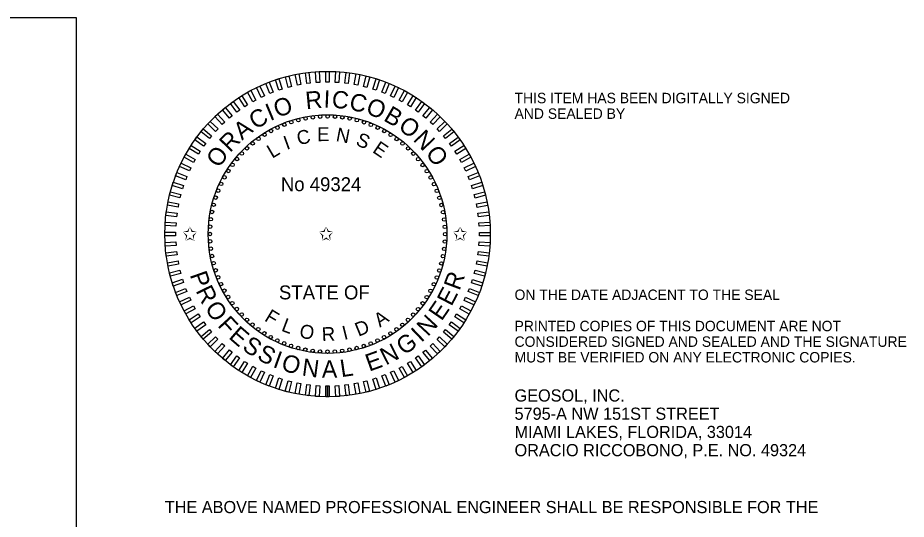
# Model space of a CAD drawing. Extents: x -816.9 to -790.1, y -2199.5 to -2184.5.
# Drawn here: x -795.17 to -790.06, y -2191.79 to -2188.9 of the extents above; entities that cross this region are included whole.
import ezdxf

# ---------------------------------------------------------------- set-up
doc = ezdxf.new("R2010")
doc.units = 0
for name, color, linetype in [('Logo_dp', 7, 'Continuous'), ('NonPlottingEle_dp', 7, 'Continuous'), ('PlotBorder_dp', 7, 'Continuous'), ('TextMisc', 7, 'Continuous')]:
    doc.layers.add(name, color=color, linetype=linetype)

msp = doc.modelspace()

# ---------------------------------------------------------------- linework, layer by layer
at = {"layer": 'Logo_dp'}
for p, q in [((-793.3999, -2191.0843), (-793.4001, -2191.0218)), ((-793.3899, -2191.0843), (-793.3901, -2191.0218)), ((-793.3799, -2191.0843), (-793.3801, -2191.0218))]:
    msp.add_line(p, q, dxfattribs=at)
for points in [[(-793.5438, -2189.2854), (-793.5637, -2189.2892), (-793.5754, -2189.2278), (-793.5555, -2189.224)], [(-793.4895, -2189.2774), (-793.5095, -2189.2799), (-793.5173, -2189.218), (-793.4973, -2189.2155)], [(-793.4347, -2189.2729), (-793.4548, -2189.2741), (-793.4587, -2189.2118), (-793.4386, -2189.2106)], [(-793.3797, -2189.2718), (-793.3999, -2189.2718), (-793.3999, -2189.2093), (-793.3797, -2189.2093)], [(-793.3248, -2189.2741), (-793.3449, -2189.2729), (-793.341, -2189.2106), (-793.3209, -2189.2118)], [(-793.2701, -2189.28), (-793.2901, -2189.2774), (-793.2823, -2189.2155), (-793.2623, -2189.218)], [(-793.2159, -2189.2892), (-793.2357, -2189.2854), (-793.224, -2189.2241), (-793.2042, -2189.2279)], [(-793.7025, -2189.3295), (-793.7213, -2189.3369), (-793.7443, -2189.2789), (-793.7255, -2189.2714)], [(-793.6506, -2189.3115), (-793.6698, -2189.3177), (-793.6891, -2189.2583), (-793.6699, -2189.2521)], [(-793.5976, -2189.2967), (-793.6172, -2189.3018), (-793.6327, -2189.2413), (-793.6132, -2189.2363)], [(-793.1624, -2189.3018), (-793.182, -2189.2968), (-793.1664, -2189.2363), (-793.1469, -2189.2413)], [(-793.1098, -2189.3178), (-793.129, -2189.3115), (-793.1097, -2189.2521), (-793.0905, -2189.2584)], [(-793.0583, -2189.337), (-793.0771, -2189.3295), (-793.0541, -2189.2715), (-793.0353, -2189.2789)], [(-793.8025, -2189.3751), (-793.8202, -2189.3848), (-793.8503, -2189.3301), (-793.8326, -2189.3204)], [(-793.7532, -2189.3507), (-793.7715, -2189.3593), (-793.7981, -2189.3028), (-793.7798, -2189.2942)], [(-793.0081, -2189.3594), (-793.0264, -2189.3508), (-792.9998, -2189.2943), (-792.9815, -2189.3029)], [(-792.9594, -2189.3849), (-792.9771, -2189.3752), (-792.947, -2189.3205), (-792.9293, -2189.3302)], [(-793.896, -2189.4329), (-793.9123, -2189.4448), (-793.949, -2189.3943), (-793.9327, -2189.3824)], [(-793.8502, -2189.4025), (-793.8672, -2189.4134), (-793.9007, -2189.3606), (-793.8836, -2189.3498)], [(-792.9124, -2189.4135), (-792.9295, -2189.4026), (-792.896, -2189.3499), (-792.879, -2189.3607)], [(-792.8673, -2189.4449), (-792.8836, -2189.433), (-792.8469, -2189.3825), (-792.8306, -2189.3944)], [(-793.9398, -2189.4661), (-793.9554, -2189.479), (-793.9952, -2189.4309), (-793.9796, -2189.418)], [(-792.8243, -2189.4791), (-792.8398, -2189.4662), (-792.8, -2189.4181), (-792.7845, -2189.431)], [(-793.9815, -2189.502), (-793.9962, -2189.5158), (-794.0389, -2189.4703), (-794.0242, -2189.4565)], [(-792.7835, -2189.5159), (-792.7982, -2189.5021), (-792.7554, -2189.4566), (-792.7407, -2189.4704)], [(-794.0208, -2189.5404), (-794.0346, -2189.5551), (-794.0801, -2189.5124), (-794.0663, -2189.4976)], [(-792.745, -2189.5552), (-792.7589, -2189.5405), (-792.7133, -2189.4978), (-792.6995, -2189.5125)], [(-794.0918, -2189.6242), (-794.1037, -2189.6406), (-794.1542, -2189.6039), (-794.1423, -2189.5875)], [(-794.0576, -2189.5812), (-794.0705, -2189.5968), (-794.1186, -2189.5569), (-794.1057, -2189.5414)], [(-792.7092, -2189.5969), (-792.722, -2189.5813), (-792.6739, -2189.5415), (-792.6611, -2189.5571)], [(-792.676, -2189.6407), (-792.6878, -2189.6244), (-792.6373, -2189.5877), (-792.6255, -2189.604)], [(-794.1232, -2189.6693), (-794.1341, -2189.6864), (-794.1868, -2189.6529), (-794.176, -2189.6359)], [(-792.6456, -2189.6865), (-792.6564, -2189.6695), (-792.6037, -2189.636), (-792.5929, -2189.6531)], [(-794.1518, -2189.7163), (-794.1615, -2189.734), (-794.2162, -2189.7039), (-794.2065, -2189.6863)], [(-792.6182, -2189.7342), (-792.6279, -2189.7165), (-792.5732, -2189.6864), (-792.5635, -2189.7041)], [(-794.1773, -2189.765), (-794.1859, -2189.7833), (-794.2424, -2189.7567), (-794.2338, -2189.7384)], [(-792.5938, -2189.7835), (-792.6024, -2189.7652), (-792.5459, -2189.7386), (-792.5373, -2189.7569)], [(-794.1997, -2189.8152), (-794.2071, -2189.834), (-794.2652, -2189.811), (-794.2578, -2189.7922)], [(-792.5726, -2189.8342), (-792.58, -2189.8154), (-792.5219, -2189.7924), (-792.5145, -2189.8112)], [(-794.2189, -2189.8667), (-794.2252, -2189.8859), (-794.2846, -2189.8666), (-794.2783, -2189.8474)], [(-792.5545, -2189.8861), (-792.5608, -2189.8669), (-792.5014, -2189.8476), (-792.4952, -2189.8668)], [(-794.2349, -2189.9193), (-794.2399, -2189.9389), (-794.3004, -2189.9234), (-794.2954, -2189.9038)], [(-792.5398, -2189.9391), (-792.5448, -2189.9195), (-792.4844, -2189.904), (-792.4793, -2189.9235)], [(-794.2475, -2189.9728), (-794.2513, -2189.9927), (-794.3126, -2189.981), (-794.3088, -2189.9611)], [(-792.5284, -2189.9929), (-792.5322, -2189.973), (-792.4709, -2189.9613), (-792.4671, -2189.9812)], [(-794.2567, -2190.027), (-794.2593, -2190.0471), (-794.3212, -2190.0392), (-794.3187, -2190.0192)], [(-792.5205, -2190.0472), (-792.523, -2190.0272), (-792.4611, -2190.0194), (-792.4585, -2190.0394)], [(-794.2626, -2190.0817), (-794.2638, -2190.1018), (-794.3261, -2190.0979), (-794.3249, -2190.0778)], [(-792.5159, -2190.102), (-792.5172, -2190.0819), (-792.4549, -2190.078), (-792.4536, -2190.0981)], [(-794.2649, -2190.1366), (-794.2649, -2190.1568), (-794.3274, -2190.1568), (-794.3274, -2190.1366)], [(-792.5149, -2190.157), (-792.5149, -2190.1368), (-792.4524, -2190.1368), (-792.4524, -2190.157)], [(-794.2638, -2190.1916), (-794.2626, -2190.2117), (-794.3249, -2190.2157), (-794.3261, -2190.1955)], [(-792.5172, -2190.2119), (-792.516, -2190.1918), (-792.4536, -2190.1957), (-792.4549, -2190.2158)], [(-794.2593, -2190.2464), (-794.2568, -2190.2664), (-794.3187, -2190.2742), (-794.3212, -2190.2542)], [(-792.523, -2190.2666), (-792.5205, -2190.2466), (-792.4586, -2190.2544), (-792.4611, -2190.2744)], [(-794.2513, -2190.3008), (-794.2475, -2190.3206), (-794.3089, -2190.3323), (-794.3127, -2190.3125)], [(-792.5323, -2190.3208), (-792.5285, -2190.301), (-792.4671, -2190.3127), (-792.4709, -2190.3325)], [(-794.24, -2190.3546), (-794.2349, -2190.3741), (-794.2954, -2190.3896), (-794.3004, -2190.3701)], [(-792.5449, -2190.3743), (-792.5399, -2190.3547), (-792.4794, -2190.3703), (-792.4844, -2190.3898)], [(-794.2252, -2190.4075), (-794.219, -2190.4267), (-794.2784, -2190.446), (-794.2846, -2190.4268)], [(-792.5608, -2190.4269), (-792.5546, -2190.4077), (-792.4952, -2190.427), (-792.5014, -2190.4462)], [(-794.2072, -2190.4595), (-794.1998, -2190.4782), (-794.2578, -2190.5012), (-794.2653, -2190.4824)], [(-792.5801, -2190.4784), (-792.5726, -2190.4596), (-792.5146, -2190.4826), (-792.522, -2190.5014)], [(-794.186, -2190.5102), (-794.1774, -2190.5284), (-794.2339, -2190.555), (-794.2425, -2190.5367)], [(-792.6025, -2190.5286), (-792.5939, -2190.5103), (-792.5374, -2190.5369), (-792.546, -2190.5552)], [(-794.1616, -2190.5594), (-794.1519, -2190.5771), (-794.2066, -2190.6072), (-794.2163, -2190.5895)], [(-792.628, -2190.5773), (-792.6183, -2190.5596), (-792.5636, -2190.5897), (-792.5733, -2190.6074)], [(-794.1342, -2190.6071), (-794.1233, -2190.6241), (-794.1761, -2190.6576), (-794.1869, -2190.6405)], [(-792.6565, -2190.6243), (-792.6457, -2190.6072), (-792.593, -2190.6407), (-792.6038, -2190.6577)], [(-794.1038, -2190.6529), (-794.0919, -2190.6692), (-794.1424, -2190.7059), (-794.1543, -2190.6896)], [(-792.688, -2190.6694), (-792.6761, -2190.653), (-792.6256, -2190.6898), (-792.6374, -2190.7061)], [(-794.0706, -2190.6967), (-794.0577, -2190.7123), (-794.1058, -2190.7521), (-794.1187, -2190.7365)], [(-792.7222, -2190.7124), (-792.7093, -2190.6969), (-792.6612, -2190.7367), (-792.674, -2190.7522)], [(-794.0347, -2190.7384), (-794.0209, -2190.7531), (-794.0664, -2190.7958), (-794.0802, -2190.7811)], [(-792.759, -2190.7532), (-792.7452, -2190.7385), (-792.6997, -2190.7813), (-792.7135, -2190.796)], [(-793.9963, -2190.7777), (-793.9816, -2190.7915), (-794.0243, -2190.837), (-794.0391, -2190.8232)], [(-793.9555, -2190.8145), (-793.9399, -2190.8274), (-793.9797, -2190.8755), (-793.9953, -2190.8627)], [(-792.84, -2190.8275), (-792.8244, -2190.8147), (-792.7846, -2190.8628), (-792.8002, -2190.8756)], [(-792.7983, -2190.7917), (-792.7836, -2190.7778), (-792.7409, -2190.8234), (-792.7556, -2190.8372)], [(-793.9125, -2190.8487), (-793.8961, -2190.8606), (-793.9328, -2190.9111), (-793.9492, -2190.8993)], [(-792.8838, -2190.8607), (-792.8675, -2190.8488), (-792.8308, -2190.8994), (-792.8471, -2190.9112)], [(-793.8674, -2190.8802), (-793.8503, -2190.891), (-793.8838, -2190.9437), (-793.9008, -2190.9329)], [(-793.8204, -2190.9087), (-793.8027, -2190.9184), (-793.8328, -2190.9731), (-793.8504, -2190.9634)], [(-792.9773, -2190.9185), (-792.9596, -2190.9088), (-792.9295, -2190.9635), (-792.9472, -2190.9732)], [(-792.9296, -2190.8911), (-792.9126, -2190.8803), (-792.8791, -2190.933), (-792.8962, -2190.9438)], [(-793.7717, -2190.9342), (-793.7534, -2190.9428), (-793.78, -2190.9993), (-793.7983, -2190.9907)], [(-793.7215, -2190.9566), (-793.7027, -2190.9641), (-793.7257, -2191.0221), (-793.7445, -2191.0147)], [(-793.0772, -2190.9641), (-793.0585, -2190.9567), (-793.0355, -2191.0148), (-793.0543, -2191.0222)], [(-793.0265, -2190.9429), (-793.0083, -2190.9343), (-792.9817, -2190.9908), (-792.9999, -2190.9994)], [(-793.67, -2190.9759), (-793.6508, -2190.9821), (-793.6701, -2191.0415), (-793.6893, -2191.0352)], [(-793.6174, -2190.9918), (-793.5978, -2190.9968), (-793.6133, -2191.0573), (-793.6329, -2191.0523)], [(-793.5639, -2191.0044), (-793.544, -2191.0082), (-793.5557, -2191.0695), (-793.5756, -2191.0658)], [(-793.5097, -2191.0137), (-793.4896, -2191.0162), (-793.4975, -2191.0781), (-793.5175, -2191.0756)], [(-793.455, -2191.0195), (-793.4348, -2191.0207), (-793.4388, -2191.0831), (-793.4589, -2191.0818)], [(-793.4001, -2191.0218), (-793.3799, -2191.0218), (-793.3799, -2191.0843), (-793.4001, -2191.0843)], [(-793.3451, -2191.0208), (-793.325, -2191.0195), (-793.321, -2191.0818), (-793.3412, -2191.0831)], [(-793.2903, -2191.0162), (-793.2703, -2191.0137), (-793.2625, -2191.0756), (-793.2825, -2191.0782)], [(-793.2359, -2191.0082), (-793.2161, -2191.0045), (-793.2044, -2191.0658), (-793.2242, -2191.0696)], [(-793.1821, -2190.9969), (-793.1626, -2190.9919), (-793.1471, -2191.0523), (-793.1666, -2191.0574)], [(-793.1292, -2190.9822), (-793.11, -2190.9759), (-793.0907, -2191.0353), (-793.1099, -2191.0415)]]:
    msp.add_lwpolyline(points, close=True, dxfattribs=at)
for centre in [(-793.5578, -2189.4905), (-793.5163, -2189.4812), (-793.4742, -2189.4746), (-793.4319, -2189.4706), (-793.3893, -2189.4693), (-793.3468, -2189.4707), (-793.3044, -2189.4748), (-793.2624, -2189.4814), (-793.2209, -2189.4908), (-793.6778, -2189.5336), (-793.6388, -2189.5167), (-793.5987, -2189.5023), (-793.18, -2189.5027), (-793.14, -2189.5171), (-793.1009, -2189.5341), (-793.7876, -2189.5984), (-793.7524, -2189.5745), (-793.7158, -2189.5529), (-793.063, -2189.5534), (-793.0264, -2189.5751), (-792.9912, -2189.5991), (-793.8213, -2189.6245), (-792.9576, -2189.6252), (-793.8834, -2189.6826), (-793.8532, -2189.6526), (-792.9257, -2189.6533), (-792.8956, -2189.6835), (-793.9376, -2189.7481), (-793.9115, -2189.7145), (-792.8675, -2189.7154), (-792.8415, -2189.7491), (-793.9616, -2189.7833), (-792.8176, -2189.7843), (-793.9833, -2189.8199), (-792.7959, -2189.8209), (-794.0196, -2189.8969), (-794.0026, -2189.8578), (-792.7767, -2189.8589), (-792.7598, -2189.8979), (-794.034, -2189.9369), (-792.7454, -2189.938), (-794.0459, -2189.9778), (-792.7336, -2189.9789), (-794.0552, -2190.0193), (-792.7243, -2190.0204), (-794.066, -2190.1037), (-794.0619, -2190.0613), (-792.7177, -2190.0625), (-792.7137, -2190.1048), (-794.0674, -2190.1462), (-792.7124, -2190.1474), (-794.0661, -2190.1888), (-792.7138, -2190.1899), (-794.0621, -2190.2312), (-792.7178, -2190.2323), (-794.0555, -2190.2732), (-794.0462, -2190.3147), (-792.7338, -2190.3158), (-792.7245, -2190.2743), (-794.0344, -2190.3556), (-792.7457, -2190.3567), (-794.02, -2190.3957), (-792.7602, -2190.3967), (-794.0031, -2190.4348), (-792.7771, -2190.4358), (-793.9838, -2190.4727), (-793.9622, -2190.5093), (-792.8182, -2190.5103), (-792.7965, -2190.4737), (-793.9383, -2190.5446), (-792.8421, -2190.5455), (-793.9122, -2190.5782), (-793.8841, -2190.6102), (-792.8964, -2190.611), (-792.8682, -2190.5791), (-793.8541, -2190.6403), (-793.8222, -2190.6684), (-792.9585, -2190.6692), (-792.9265, -2190.641), (-793.7885, -2190.6946), (-793.7534, -2190.7185), (-793.0274, -2190.7191), (-792.9921, -2190.6952), (-793.7168, -2190.7402), (-793.6788, -2190.7596), (-793.6398, -2190.7765), (-793.141, -2190.7769), (-793.1019, -2190.76), (-793.064, -2190.7408), (-793.5998, -2190.7909), (-793.5589, -2190.8029), (-793.5174, -2190.8122), (-793.4754, -2190.8189), (-793.433, -2190.8229), (-793.3899, -2190.8243), (-793.3479, -2190.823), (-793.3055, -2190.819), (-793.2635, -2190.8124), (-793.222, -2190.8031), (-793.1811, -2190.7913)]:
    msp.add_circle(centre, 0.01, dxfattribs=at)
at = {"layer": 'NonPlottingEle_dp'}
for radius in [0.9375, 0.6875]:
    msp.add_circle((-793.3899, -2190.1468), radius, dxfattribs=at)
at = {"layer": 'PlotBorder_dp'}
msp.add_lwpolyline([(-811.3358, -2199.5006), (-794.8358, -2199.5006), (-794.8358, -2188.9006), (-811.3358, -2188.9006)], close=True, dxfattribs=at)

# ---------------------------------------------------------------- texts
at = {"layer": 'Logo_dp'}
for s, height, rotation, p in [('R', 0.1, 5.3723, (-793.5127, -2189.4277)), ('I', 0.1, 357.5509, (-793.4137, -2189.4176)), ('C', 0.1, 354.0177, (-793.3688, -2189.4175)), ('O', 0.1, 19.1125, (-793.68, -2189.4774)), ('C', 0.1, 346.2809, (-793.2708, -2189.427)), ('O', 0.1, 338.5441, (-793.175, -2189.4496)), ('C', 0.1, 30.3825, (-793.8053, -2189.547)), ('I', 0.1, 22.6457, (-793.7207, -2189.4966)), ('B', 0.1, 329.8833, (-793.0724, -2189.4899)), ('O', 0.1, 322.2793, (-792.9883, -2189.5377)), ('A', 0.1, 38.1495, (-793.8825, -2189.6087)), ('E', 0.08, 0.4186, (-793.4496, -2189.6117)), ('N', 0.08, 349.2914, (-793.3452, -2189.6103)), ('R', 0.1, 45.9708, (-793.9512, -2189.6807)), ('I', 0.08, 20.0117, (-793.6256, -2189.6627)), ('C', 0.08, 12.2025, (-793.5576, -2189.6352)), ('S', 0.08, 337.0221, (-793.2322, -2189.632)), ('N', 0.1, 313.6185, (-792.9011, -2189.6051)), ('L', 0.08, 30.4021, (-793.709, -2189.7132)), ('E', 0.08, 325.8663, (-793.1356, -2189.6722)), ('O', 0.1, 54.6317, (-794.015, -2189.7705)), ('O', 0.1, 305.3683, (-792.8285, -2189.6809)), ('P', 0.1, 289.4055, (-794.1846, -2190.3814)), ('R', 0.1, 69.5134, (-792.6297, -2190.4765)), ('R', 0.1, 296.1458, (-794.1516, -2190.473)), ('E', 0.1, 62.4712, (-792.6759, -2190.5672)), ('O', 0.1, 303.9671, (-794.1001, -2190.5737)), ('E', 0.1, 55.4289, (-792.7328, -2190.6516)), ('F', 0.08, 328.7241, (-793.7579, -2190.6434)), ('A', 0.08, 34.4992, (-793.088, -2190.6862)), ('N', 0.1, 47.1788, (-792.812, -2190.7407)), ('F', 0.1, 312.628, (-794.0277, -2190.6757)), ('L', 0.08, 339.2916, (-793.6606, -2190.7025)), ('D', 0.08, 22.0128, (-793.2118, -2190.7387)), ('E', 0.1, 319.0783, (-793.9643, -2190.744)), ('O', 0.08, 349.6821, (-793.556, -2190.7422)), ('R', 0.08, 2.3398, (-793.4215, -2190.7641)), ('I', 0.08, 14.2037, (-793.2939, -2190.7574)), ('I', 0.1, 43.6456, (-792.8497, -2190.7751)), ('S', 0.1, 326.1206, (-793.8867, -2190.81)), ('G', 0.1, 35.1115, (-792.9489, -2190.8483)), ('S', 0.1, 333.193, (-793.8013, -2190.8661)), ('E', 0.1, 19.8191, (-793.1496, -2190.9398)), ('N', 0.1, 26.8614, (-793.0542, -2190.9044)), ('I', 0.1, 340.2654, (-793.7096, -2190.9113)), ('O', 0.1, 343.7986, (-793.6619, -2190.9295)), ('N', 0.1, 352.4595, (-793.5409, -2190.9615)), ('L', 0.1, 8.4767, (-793.3102, -2190.9716)), ('A', 0.1, 0.7097, (-793.4224, -2190.9748))]:
    msp.add_text(s, height=height, rotation=rotation, dxfattribs=at).set_placement(p)
for s, p in [('No 49324', (-793.6588, -2189.8996)), ('✩', (-794.2249, -2190.1848)), ('✩', (-793.4401, -2190.1848)), ('✩', (-792.6683, -2190.1848)), ('STATE OF', (-793.6696, -2190.523))]:
    msp.add_text(s, height=0.08, dxfattribs=at).set_placement(p)
at = {"layer": 'TextMisc'}
for s, height, p in [('THIS ITEM HAS BEEN DIGITALLY SIGNED ', 0.06, (-792.3122, -2189.393)), ('AND SEALED BY', 0.06, (-792.3122, -2189.483)), ('ON THE DATE ADJACENT TO THE SEAL', 0.06, (-792.3122, -2190.5264)), ('PRINTED COPIES OF THIS DOCUMENT ARE NOT ', 0.06, (-792.3122, -2190.7064)), ('CONSIDERED SIGNED AND SEALED AND THE SIGNATURE ', 0.06, (-792.3122, -2190.7964)), ('MUST BE VERIFIED ON ANY ELECTRONIC COPIES.', 0.06, (-792.3122, -2190.8864)), ('GEOSOL, INC.', 0.07, (-792.3122, -2191.1116)), ('5795-A NW 151ST STREET', 0.07, (-792.3122, -2191.2166)), ('MIAMI LAKES, FLORIDA, 33014', 0.07, (-792.3122, -2191.3216)), ('ORACIO RICCOBONO, P.E. NO. 49324', 0.07, (-792.3122, -2191.4266)), ('THE ABOVE NAMED PROFESSIONAL ENGINEER SHALL BE RESPONSIBLE FOR THE ', 0.07, (-794.3274, -2191.7544))]:
    msp.add_text(s, height=height, dxfattribs=at).set_placement(p)

doc.saveas('drawing.dxf')
